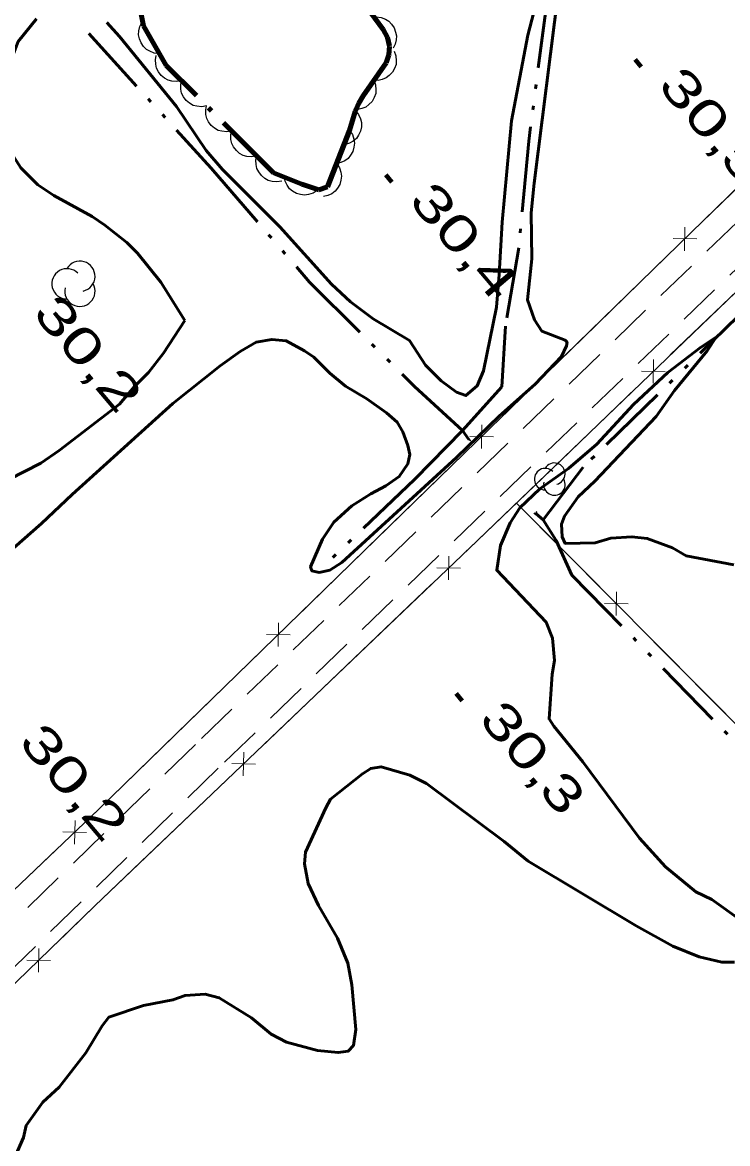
# Model space of a CAD drawing. Extents: x 386081 to 389416, y 5130568 to 5134082.
# Drawn here: x 388688.2 to 388747.8, y 5131833.5 to 5131928.4 of the extents above; entities that cross this region are included whole.
import ezdxf

# ---------------------------------------------------------------- set-up
doc = ezdxf.new("R2010")
doc.units = 0
doc.header["$LTSCALE"] = 1.2
for name, pattern in [('DASH_DOUBLE_DOT', [9.2, 5, -1.2, 0.3, -1.2, 0.3, -1.2]), ('DOT_DASHED', [7.7, 5, -1.2, 0.3, -1.2]), ('MEDIUM_DASHED', [4.5, 3, -1.5])]:
    doc.linetypes.add(name, pattern=pattern)
for name, color, linetype, lineweight in [('1', 7, 'Continuous', 53), ('19', 7, 'Continuous', 13), ('26', 7, 'Continuous', 35), ('3', 7, 'Continuous', 140), ('37', 7, 'Continuous', 13), ('4', 7, 'DASH_DOUBLE_DOT', 53), ('44', 7, 'Continuous', 25)]:
    doc.layers.add(name, color=color, linetype=linetype, lineweight=lineweight)

msp = doc.modelspace()

# ---------------------------------------------------------------- linework, layer by layer
at = {"layer": '1'}
for points in [[(388732.16, 5131931.98), (388730.95, 5131927.3), (388729.57, 5131920.05), (388728.78, 5131911.48), (388728.53, 5131907.05), (388728.29, 5131904.29), (388727.2, 5131898.9), (388726.66, 5131897.64), (388725.7, 5131896.8), (388724.92, 5131897.1), (388723.61, 5131898.05), (388722.29, 5131899.37), (388720.92, 5131901.46), (388717.86, 5131903.31), (388715.95, 5131904.74), (388714.33, 5131906.24), (388709.97, 5131911.08), (388705.12, 5131915.93), (388703.74, 5131917.54), (388701.23, 5131921.25), (388696.38, 5131927.18), (388695.31, 5131928.37)], [(388681.09, 5131878.36), (388689.8, 5131885.99), (388692.38, 5131888.45), (388700.9, 5131896.14), (388704.92, 5131899.33), (388706.6, 5131900.53), (388707.97, 5131901.31), (388709.29, 5131901.55), (388710.49, 5131901.44), (388712.05, 5131900.6), (388712.83, 5131900.06), (388714.2, 5131898.69), (388715.52, 5131897.61), (388717.31, 5131896.54), (388718.99, 5131895.34), (388719.89, 5131894.57), (388720.37, 5131893.73), (388720.78, 5131892.59), (388720.96, 5131891.81), (388720.78, 5131891.03), (388720.06, 5131889.95), (388718.92, 5131889.17), (388717.66, 5131888.51), (388716.04, 5131887.49), (388714.54, 5131886.11), (388713.58, 5131884.67), (388712.56, 5131882.33), (388712.68, 5131881.97), (388713.28, 5131881.85), (388714.18, 5131882.03), (388715.2, 5131882.69), (388724.92, 5131891.58), (388728.51, 5131895.07), (388731.57, 5131897.77), (388733.79, 5131900.11), (388734.21, 5131901.01), (388734.27, 5131901.31), (388734.09, 5131901.49), (388732.12, 5131902.26), (388731.52, 5131903.22), (388730.92, 5131904.9), (388731.29, 5131908.37), (388731.23, 5131912.27), (388731.48, 5131914.78), (388733.53, 5131931.08)], [(388689.37, 5131928.66), (388687.81, 5131926.74), (388687.09, 5131924.82), (388686.43, 5131922.36), (388686.48, 5131919.67), (388687.2, 5131917.39), (388688.04, 5131916.07)], [(388688.04, 5131916.07), (388689.47, 5131914.64), (388690.85, 5131913.74), (388694.09, 5131911.95), (388695.16, 5131911.23), (388697.02, 5131909.74), (388697.92, 5131908.84), (388699.89, 5131906.39), (388701.93, 5131903.16)], [(388701.93, 5131903.16), (388700.12, 5131900.4), (388698.86, 5131898.77), (388697.66, 5131897.57), (388696.4, 5131896.07), (388691.3, 5131892.17), (388689.74, 5131891.08), (388687.04, 5131889.7)], [(388748.37, 5131882.48), (388744.35, 5131883.25), (388743.17, 5131883.92), (388741.05, 5131884.72), (388739.75, 5131884.86), (388737.96, 5131884.74), (388736.65, 5131884.34), (388734.11, 5131884.3), (388733.84, 5131884.86), (388733.78, 5131885.93), (388734.05, 5131886.61), (388735.21, 5131888.23), (388736.6, 5131889.58), (388741.79, 5131895.05), (388743.35, 5131897.24), (388746.12, 5131900.59), (388746.88, 5131901.76), (388745.54, 5131900.88), (388742.8, 5131898.76), (388739.89, 5131896.05), (388736.78, 5131892.69), (388734.39, 5131890.63), (388731.95, 5131888.93), (388730.26, 5131887.32), (388729.45, 5131886.04), (388728.63, 5131884.12), (388728.31, 5131882.03), (388732.5, 5131877.63), (388733.02, 5131876.28), (388733.2, 5131874.41), (388733.01, 5131873.25), (388732.74, 5131869.46), (388733.13, 5131868.84), (388735.6, 5131865.82), (388740.38, 5131859.37), (388742.59, 5131856.95)], [(388748.42, 5131848.9), (388747.36, 5131848.88), (388745.44, 5131849.34), (388743.2, 5131850.24), (388740.12, 5131851.95), (388730.98, 5131857.42), (388728.95, 5131859.08), (388722.36, 5131864.01), (388720.95, 5131864.7), (388718.53, 5131865.41), (388717.65, 5131865.28), (388716.95, 5131864.82), (388714.26, 5131862.68), (388713.85, 5131861.94), (388712.13, 5131858.19), (388712.04, 5131857.19), (388712.36, 5131855.55), (388713.22, 5131853.68), (388714.83, 5131850.92), (388715.72, 5131848.8), (388716.04, 5131846.98), (388716.39, 5131843.19), (388716.19, 5131841.84), (388715.74, 5131841.36), (388714.89, 5131841.24), (388713.16, 5131841.42), (388710.53, 5131842.12), (388709.24, 5131842.8), (388707.56, 5131844.18), (388704.83, 5131845.88), (388703.64, 5131846.18), (388701.94, 5131846.08), (388700.92, 5131845.7), (388698.42, 5131845.21), (388695.48, 5131844.23), (388694.92, 5131843.51), (388693.55, 5131841.21), (388691.3, 5131838.32), (388689.9, 5131837.05), (388688.51, 5131835.08), (388688.26, 5131834.05), (388687.25, 5131831.74)], [(388742.59, 5131856.95), (388745.17, 5131854.83), (388746.51, 5131854.19), (388748.99, 5131852.4)]]:
    msp.add_lwpolyline(points, dxfattribs=at)
at = {"layer": '19', "linetype": 'MEDIUM_DASHED'}
for points in [[(388252.68, 5131430.25), (388278.55, 5131454.69), (388293.31, 5131469.55), (388320.68, 5131497.53), (388341.35, 5131518.12), (388360.77, 5131537.04), (388380.1, 5131555.67), (388403.27, 5131578.3), (388455.49, 5131628.78), (388492.58, 5131664.22), (388519.73, 5131690.42), (388546.92, 5131716.26), (388576.13, 5131744.42), (388620.84, 5131788.16), (388642.73, 5131809.41), (388661.6, 5131828.09), (388684.76, 5131849.73), (388703.32, 5131867.8), (388787.8, 5131949.19)], [(388254.63, 5131428.24), (388280.5, 5131452.69), (388295.31, 5131467.59), (388322.67, 5131495.55), (388343.31, 5131516.12), (388362.72, 5131535.03), (388382.05, 5131553.66), (388405.23, 5131576.29), (388457.43, 5131626.76), (388494.52, 5131662.2), (388521.66, 5131688.4), (388548.86, 5131714.23), (388578.08, 5131742.41), (388622.8, 5131786.15), (388644.69, 5131807.41), (388663.54, 5131826.08), (388686.7, 5131847.7), (388705.27, 5131865.79), (388789.75, 5131947.18)]]:
    msp.add_lwpolyline(points, dxfattribs=at)
at = {"layer": '26'}
for p, q in [((388725.89, 5131893.16), (388725.95, 5131893.23)), ((388725.89, 5131893.16), (388725.95, 5131893.23)), ((388726.03, 5131893.02), (388725.89, 5131893.16)), ((388726.03, 5131893.02), (388725.89, 5131893.16)), ((388726.03, 5131893.02), (388726.1, 5131893.09)), ((388726.03, 5131893.02), (388726.1, 5131893.09)), ((388731.7, 5131886.91), (388731.64, 5131886.98)), ((388731.7, 5131886.91), (388731.64, 5131886.98)), ((388731.55, 5131886.77), (388731.49, 5131886.85)), ((388731.55, 5131886.77), (388731.49, 5131886.85)), ((388731.7, 5131886.91), (388731.55, 5131886.77)), ((388731.7, 5131886.91), (388731.55, 5131886.77))]:
    msp.add_line(p, q, dxfattribs=at)
at = {"layer": '3'}
for p, q in [((388740.02, 5131925.22), (388740.53, 5131924.61)), ((388718.94, 5131915.47), (388719.45, 5131914.86)), ((388724.87, 5131871.61), (388725.38, 5131871))]:
    msp.add_line(p, q, dxfattribs=at)
at = {"layer": '37'}
for p, q in [((388745.66, 5131911.46), (388752.83, 5131918.43)), ((388744.21, 5131909.06), (388744.24, 5131911.06)), ((388745.23, 5131910.05), (388743.23, 5131910.08)), ((388735.63, 5131901.69), (388742.79, 5131908.67)), ((388743, 5131900.24), (388750.21, 5131907.17)), ((388728.46, 5131894.72), (388735.63, 5131901.69)), ((388741.54, 5131897.85), (388741.58, 5131899.85)), ((388742.56, 5131898.83), (388740.56, 5131898.87)), ((388732.91, 5131890.54), (388740.12, 5131897.47)), ((388727.01, 5131892.32), (388727.04, 5131894.33)), ((388728.03, 5131893.31), (388726.03, 5131893.34)), ((388718.43, 5131884.96), (388725.59, 5131891.93)), ((388729.98, 5131887.72), (388737.03, 5131880.62)), ((388711.26, 5131877.98), (388718.43, 5131884.96)), ((388724.23, 5131881.23), (388724.27, 5131883.23)), ((388725.25, 5131882.2), (388723.25, 5131882.25)), ((388715.57, 5131873.94), (388722.8, 5131880.85)), ((388738.43, 5131878.2), (388738.44, 5131880.21)), ((388737.43, 5131879.21), (388739.44, 5131879.2)), ((388709.81, 5131875.59), (388709.84, 5131877.59)), ((388739.84, 5131877.79), (388746.89, 5131870.69)), ((388710.83, 5131876.57), (388708.83, 5131876.6)), ((388701.23, 5131868.22), (388708.39, 5131875.19)), ((388708.34, 5131867.04), (388715.57, 5131873.94)), ((388706.87, 5131864.66), (388706.91, 5131866.66)), ((388707.89, 5131865.63), (388705.89, 5131865.68)), ((388698.21, 5131857.37), (388705.44, 5131864.28)), ((388692.58, 5131858.87), (388692.63, 5131860.87)), ((388693.61, 5131859.85), (388691.6, 5131859.9)), ((388683.91, 5131851.6), (388691.16, 5131858.49)), ((388689.55, 5131848.05), (388689.58, 5131850.05)), ((388690.56, 5131849.03), (388688.56, 5131849.06))]:
    msp.add_line(p, q, dxfattribs=at)
for points in [[(388629.37, 5131790.46), (388658.44, 5131818.88), (388694.31, 5131853.65), (388725.97, 5131883.87), (388794.38, 5131949.62), (388818.35, 5131973.24), (388832.72, 5131986.78), (388860.11, 5132013.32), (388894.33, 5132046.92), (388909.61, 5132061.8), (388920.73, 5132072.18), (388927.36, 5132077.58), (388931.52, 5132079.34), (388944.36, 5132065.63), (388962.9, 5132046.61), (388980.53, 5132028.18), (388994.45, 5132013.33)], [(388631.76, 5131801.96), (388694.62, 5131861.79), (388753.29, 5131918.88), (388797.98, 5131961.7), (388839.32, 5132002.36), (388871.07, 5132032.96)], [(388725.7, 5131883.61), (388725.97, 5131883.87), (388732.91, 5131890.54)], [(388729.98, 5131887.72), (388749.66, 5131867.9), (388781.21, 5131834.22)], [(388746.89, 5131870.69), (388749.66, 5131867.9), (388753.81, 5131863.47)], [(388694.05, 5131861.25), (388694.62, 5131861.79), (388701.23, 5131868.22)], [(388691, 5131850.44), (388694.31, 5131853.65), (388698.21, 5131857.37)]]:
    msp.add_lwpolyline(points, dxfattribs=at)
at = {"layer": '4'}
msp.add_line((388731.63, 5131886.84), (388732.24, 5131886.29), dxfattribs=at)
for points in [[(388773.15, 5132015.17), (388765.42, 5132007.66), (388760.66, 5132002.63), (388757.5, 5131998.78), (388753.93, 5131989.96), (388742.92, 5131961.42), (388736.56, 5131944.32), (388732.61, 5131930.48), (388731.02, 5131918.33), (388730.18, 5131909.3), (388729.04, 5131902.67), (388728.73, 5131897.55), (388725.42, 5131893.86), (388721.38, 5131889.74), (388714.28, 5131882.95)], [(388811.2, 5131963.96), (388797.29, 5131950.76), (388735.63, 5131890.76), (388732.24, 5131886.29), (388733.34, 5131884.55), (388734.67, 5131881.63), (388751.12, 5131864.8), (388769.94, 5131844.57), (388778.12, 5131835.65)], [(388693.81, 5131927.42), (388704.14, 5131916.04), (388712.48, 5131906.4), (388721.35, 5131897.58), (388725.42, 5131893.86), (388725.96, 5131893.09)]]:
    msp.add_lwpolyline(points, dxfattribs=at)
at = {"layer": '44', "linetype": 'DOT_DASHED', "lineweight": 90}
for points in [[(388716.26, 5131932.75), (388716.36, 5131931.96), (388716.91, 5131930.41), (388717.3, 5131929.68), (388718.69, 5131927.76), (388719.06, 5131927.09), (388719.24, 5131926.36), (388719.19, 5131925.63), (388718.95, 5131924.95), (388717, 5131922.17), (388716.64, 5131921.53), (388716.34, 5131920.83), (388715.86, 5131919.22)], [(388715.86, 5131919.22), (388713.98, 5131914.45), (388713.26, 5131914.21), (388711.83, 5131914.68), (388709.43, 5131915.64), (388700.34, 5131924.73), (388698.42, 5131928.08), (388697.95, 5131930.48)]]:
    msp.add_lwpolyline(points, dxfattribs=at)
at = {"layer": '44'}
for points in [[(388718.1, 5131928.83), (388718.52, 5131928.79), (388718.89, 5131928.64), (388719.18, 5131928.47), (388719.42, 5131928.22), (388719.63, 5131927.91), (388719.76, 5131927.55), (388719.83, 5131927.23), (388719.8, 5131926.88), (388719.71, 5131926.52), (388719.55, 5131926.2)], [(388699.76, 5131925.74), (388699.34, 5131925.77), (388698.96, 5131925.92), (388698.67, 5131926.08), (388698.43, 5131926.33), (388698.22, 5131926.63), (388698.08, 5131926.99), (388698, 5131927.31), (388698.03, 5131927.66), (388698.11, 5131928.02), (388698.27, 5131928.35)], [(388719.63, 5131925.92), (388719.78, 5131925.53), (388719.81, 5131925.13), (388719.79, 5131924.8), (388719.67, 5131924.47), (388719.48, 5131924.15), (388719.21, 5131923.88), (388718.96, 5131923.67), (388718.63, 5131923.54), (388718.27, 5131923.46), (388717.91, 5131923.47)], [(388701.63, 5131923.44), (388701.22, 5131923.36), (388700.82, 5131923.4), (388700.5, 5131923.48), (388700.2, 5131923.65), (388699.91, 5131923.89), (388699.69, 5131924.2), (388699.53, 5131924.49), (388699.46, 5131924.83), (388699.45, 5131925.2), (388699.51, 5131925.56)], [(388703.76, 5131921.31), (388703.35, 5131921.23), (388702.94, 5131921.28), (388702.62, 5131921.35), (388702.32, 5131921.53), (388702.03, 5131921.77), (388701.81, 5131922.08), (388701.65, 5131922.37), (388701.58, 5131922.71), (388701.57, 5131923.08), (388701.63, 5131923.44)], [(388717.91, 5131923.47), (388718.06, 5131923.08), (388718.09, 5131922.67), (388718.07, 5131922.34), (388717.94, 5131922.01), (388717.76, 5131921.69), (388717.49, 5131921.42), (388717.24, 5131921.21), (388716.91, 5131921.08), (388716.55, 5131921.01), (388716.19, 5131921.01)], [(388705.88, 5131919.19), (388705.47, 5131919.11), (388705.06, 5131919.16), (388704.74, 5131919.23), (388704.44, 5131919.41), (388704.16, 5131919.65), (388703.93, 5131919.96), (388703.77, 5131920.24), (388703.7, 5131920.59), (388703.69, 5131920.96), (388703.76, 5131921.31)], [(388716.36, 5131920.91), (388716.63, 5131920.58), (388716.78, 5131920.21), (388716.87, 5131919.89), (388716.86, 5131919.54), (388716.78, 5131919.18), (388716.61, 5131918.83), (388716.44, 5131918.56), (388716.17, 5131918.33), (388715.85, 5131918.14), (388715.51, 5131918.03)], [(388708, 5131917.07), (388707.59, 5131916.99), (388707.18, 5131917.03), (388706.86, 5131917.11), (388706.56, 5131917.29), (388706.28, 5131917.53), (388706.05, 5131917.84), (388705.89, 5131918.12), (388705.82, 5131918.47), (388705.81, 5131918.84), (388705.88, 5131919.19)], [(388715.86, 5131919.22), (388716.1, 5131918.88), (388716.22, 5131918.49), (388716.28, 5131918.16), (388716.23, 5131917.81), (388716.13, 5131917.46), (388715.93, 5131917.13), (388715.73, 5131916.87), (388715.45, 5131916.67), (388715.11, 5131916.51), (388714.76, 5131916.43)], [(388710.12, 5131914.95), (388709.71, 5131914.87), (388709.31, 5131914.91), (388708.98, 5131914.99), (388708.68, 5131915.17), (388708.4, 5131915.41), (388708.18, 5131915.72), (388708.02, 5131916), (388707.95, 5131916.35), (388707.93, 5131916.72), (388708, 5131917.07)], [(388714.76, 5131916.43), (388715, 5131916.08), (388715.12, 5131915.7), (388715.17, 5131915.37), (388715.13, 5131915.02), (388715.03, 5131914.67), (388714.83, 5131914.34), (388714.63, 5131914.08), (388714.35, 5131913.88), (388714.01, 5131913.72), (388713.66, 5131913.64)], [(388713.12, 5131914.16), (388712.78, 5131913.93), (388712.39, 5131913.81), (388712.06, 5131913.75), (388711.71, 5131913.8), (388711.36, 5131913.9), (388711.03, 5131914.1), (388710.77, 5131914.3), (388710.57, 5131914.59), (388710.41, 5131914.93), (388710.34, 5131915.28)]]:
    msp.add_lwpolyline(points, dxfattribs=at)
for centre, radius, start, end in [((388693.044, 5131906.898), 1.278, 282.26917, 149.72626), ((388691.945, 5131906.259), 1.278, 44.11537, 269.80396), ((388693.044, 5131905.62), 1.278, 166.93686, 29.62122), ((388733.19, 5131890.196), 0.91, 282.26917, 149.72626), ((388733.19, 5131890.196), 0.91, 282.26917, 149.72626), ((388732.407, 5131889.741), 0.91, 44.11537, 269.80396), ((388732.407, 5131889.741), 0.91, 44.11537, 269.80396), ((388733.19, 5131889.286), 0.91, 166.93686, 29.62122), ((388733.19, 5131889.286), 0.91, 166.93686, 29.62122)]:
    msp.add_arc(centre, radius, start, end, dxfattribs=at)

# ---------------------------------------------------------------- texts
at = {"layer": '3'}
for s, width, p in [('30,5   ', 1.45, (388741.85, 5131923)), ('30,4   ', 1.45, (388720.77, 5131913.25)), ('30,2   ', 1.45, (388688.95, 5131903.73)), ('30,3   ', 1.4, (388726.7, 5131869.39)), ('30,2   ', 1.45, (388687.76, 5131867.47))]:
    msp.add_text(s, height=3, rotation=310.294, dxfattribs=dict(at, width=width)).set_placement(p)

doc.saveas('drawing.dxf')
